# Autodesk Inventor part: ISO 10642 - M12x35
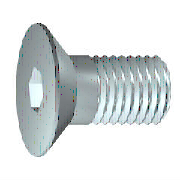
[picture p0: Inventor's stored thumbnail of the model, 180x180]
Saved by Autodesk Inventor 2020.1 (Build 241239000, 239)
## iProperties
Created: 2019-01
Part Number: ISO 10642 - M12x35
Material: Stahl, weich
Description: Senkschrauben mit Innensechskant
Document SubType Name: Modeling
Standard: ISO 10642
Designer: lutzd
Standards Organization: ISO
Language: de-DE
Size Designation: M12x35
Categories: <MemberInstance><Categories><Category DisplayName="Verbindungselemente" InternalName="e4da775c-781d-43d5-af7c-5136215cf5a6" Mnemonic="FSTN"><Category DisplayNam
Mass: 37.405 g
Surface Area: 22.6309 cm^2
Volume: 4.76496 cm^3
Density: 7.85 g/cm^3
Appearance: Halbpoliert
IsCustomPart: 0
Author: lutzd
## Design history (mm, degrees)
node "WorkPoint1"
sketch "Skizze2"
  geometry: L1 (-6, -35)-(0, -35); L2 (-6, -6.5)-(-6, -35); L3 (-12, -0.5)-(-6, -6.5); L4 (-12, 0)-(-12, -0.5); L5 (0, 0)-(-12, 0); L6 (0, -35)-(0, 0); L7 (0, -35)-(0, 0); L8 (0, -42)-(0, 7) reference; L9 (2.4, 0)-(-14.4, 0) reference
  constraints: 14 end point, 3 vertical, 2 horizontal
  dimensions: "d3" = 12 distance of L5.start L4.start (= 0.5 x dk); "d5" = 6 distance of L1.start L1.end (= 0.5 x NND); "d7" = 35 distance of L1.end L5.start (= NLG); "ParC" = 0.5 distance of L4.start L3.start; "d22" = 0 distance between parallel lines of L8 L6; "d23" = 0 distance between parallel lines of L9 L5; "d43" = 45 deg angle of L6 L3 (= 0.5 x ang)
revolve "Drehung1" stored, may be unused: angle "d8" = 360 deg
node "MSC_A1"
node "MSC_PF1"
node "MSC_PT1"
body "Solid1"
node "Skizze1"
sketch "Skizze3"
  geometry: L1 (-4, 2.309)-(-4, -2.309); L2 (0, 4.619)-(-4, 2.309); L3 (4, 2.309)-(0, 4.619); L4 (4, -2.309)-(4, 2.309); L5 (0, -4.619)-(4, -2.309); L6 (-4, -2.309)-(0, -4.619); C1 r 4 at (0, 0); C2 r 6 at (0, 0) reference
  constraints: 12 end point, 6 tangent, 2 parallel, 2 vertical, 1 centre point, 1 concentric
  dimensions: "d11" = 8 diameter of C1 (= ParS); "d13" = 120 deg angle of L1 L2; "d15" = 120 deg angle of L6 L1
extrude "Extrusion1" cut sketch "Skizze3" distance "d16" = 4.6 (= ParT); taper "d17" = 0 deg
fillet "Rundung1" dims "d18" = 1 (= r)
chamfer "Fase1" distance "d19" = 0.875 (= 0.5 x PTC); stored, may be unused: angle "d20" = 45 deg, second distance "d39" = 0.875 (= 0.5 x PTC)
feature "Gewinde1" dims "d35" = 0, "b" = 25
other parameters: "NND" = 12 [user parameter; used in 2 equation terms], "PTC" = 1.75 [user parameter; used in 2 equation terms], "dk" = 24 [user parameter; used in 1 equation term], "ParK" = 6.5 [user parameter], "ParS" = 8 [user parameter; used in 1 equation term], "ParT" = 4.6 [user parameter; used in 1 equation term], "r" = 1 [user parameter; used in 1 equation term], "NLG" = 35 [user parameter; used in 1 equation term], "d0" = 45 deg (derived), "d2" = 3 (derived), "d4" = 1.5 (derived), "d6" = 8 (derived), "d9" = 0, "d10" = 2 (derived), "d12" = 120 deg (derived), "d14" = 120 deg (derived), "d37" = 0, "d38" = 0, "d40" = 0, "d41" = 0, "d42" = 0, "ang" = 90 deg [user parameter; used in 1 equation term], "THREADDIA" = 12 (= NND) [user parameter]
